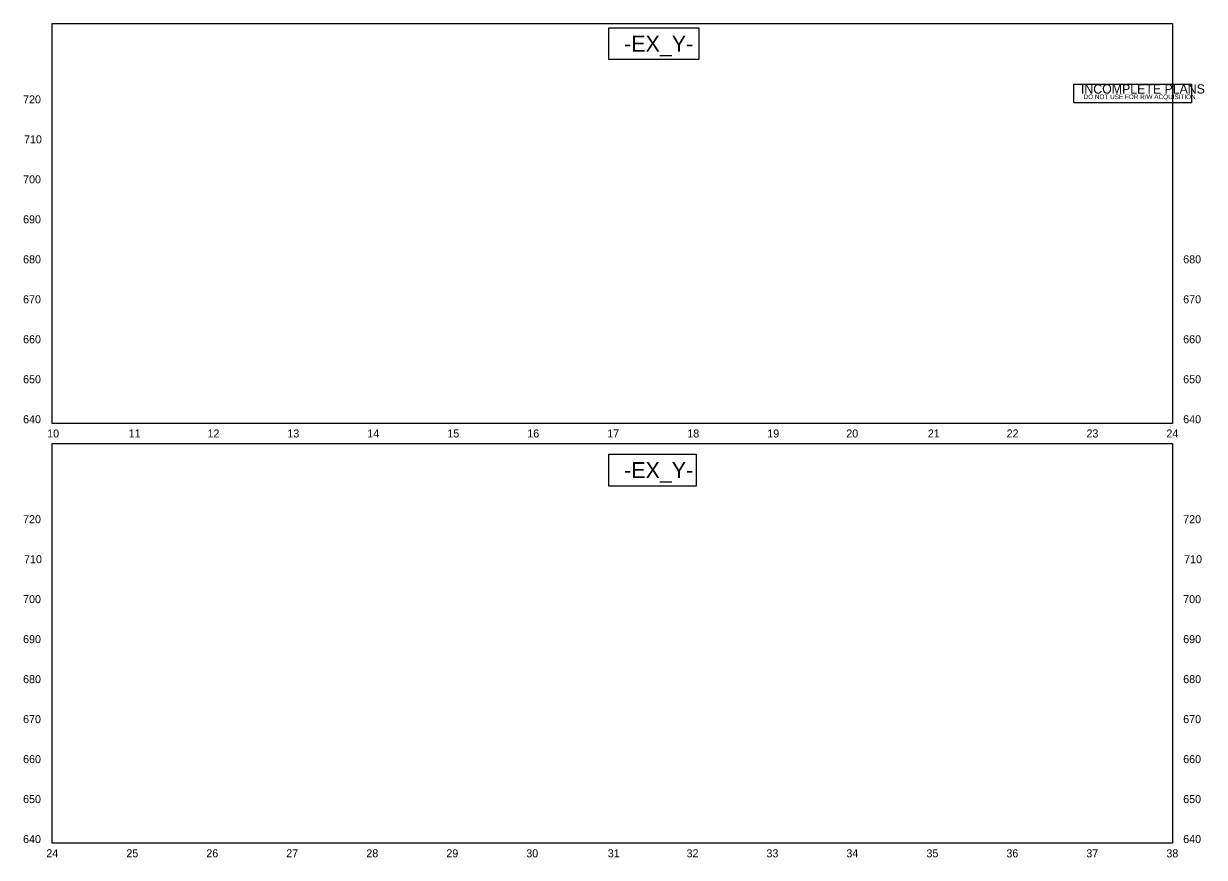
# Model space of a CAD drawing. Extents: x 2472548 to 2478566, y 619381 to 625389.
# Drawn here: x 2477090 to 2478566, y 620488 to 621531 of the extents above; entities that cross this region are included whole.
import ezdxf

# ---------------------------------------------------------------- set-up
doc = ezdxf.new("R2010")
doc.units = 0
for name, color, linetype in [('Default', 7, 'Continuous'), ('ENG SEALS CELL', 7, 'Continuous'), ('Prop Grid Mask', 7, 'Continuous'), ('Prop VPI Label', 7, 'Continuous'), ('Scratch_Level_3', 7, 'Continuous'), ('Sheet PE Seal Cell', 7, 'Continuous')]:
    doc.layers.add(name, color=color, linetype=linetype)

msp = doc.modelspace()

# ---------------------------------------------------------------- linework, layer by layer
at = {"layer": 'Default'}
msp.add_lwpolyline([(2478402.4, 621432), (2478402.4, 621455.5), (2478549.4, 621455.5), (2478549.4, 621432)], close=True, dxfattribs=at)
at = {"layer": 'ENG SEALS CELL'}
for points in [[(2477125.6, 621531.1), (2478525.6, 621531.1), (2478525.6, 621031.1), (2477125.6, 621031.1)], [(2477125.6, 621006.1), (2478525.6, 621006.1), (2478525.6, 620506.1), (2477125.6, 620506.1)]]:
    msp.add_lwpolyline(points, close=True, dxfattribs=at)
at = {"layer": 'Prop Grid Mask'}
for points in [[(2477821.2, 621525.9), (2477933.8, 621525.9), (2477933.8, 621486.1), (2477821.2, 621486.1)], [(2477821.2, 620992.7), (2477930.5, 620992.7), (2477930.5, 620952.8), (2477821.2, 620952.8)]]:
    msp.add_lwpolyline(points, close=True, dxfattribs=at)

# ---------------------------------------------------------------- texts
at = {"layer": 'Default'}
for s, height, p in [('INCOMPLETE PLANS', 11.52, (2478411.3, 621443.7)), ('DO NOT USE FOR R/W ACQUISITION', 5.76, (2478414.6, 621436.7))]:
    msp.add_text(s, height=height, dxfattribs=at).set_placement(p)
at = {"layer": 'Prop VPI Label'}
for p in [(2477840.4, 621496), (2477840.4, 620962.8)]:
    msp.add_text('-EX_Y-', height=20, rotation=0.0003, dxfattribs=at).set_placement(p)
at = {"layer": 'Scratch_Level_3'}
for s, p in [('10', (2477119.2, 621013.6)), ('11', (2477221.1, 621013.6)), ('12', (2477319.6, 621013.6)), ('13', (2477419.4, 621013.6)), ('14', (2477519.3, 621013.6)), ('15', (2477619.4, 621013.6)), ('16', (2477719.3, 621013.6)), ('17', (2477819.2, 621013.6)), ('18', (2477919.3, 621013.6)), ('19', (2478019.3, 621013.6)), ('20', (2478118, 621013.6)), ('21', (2478219.9, 621013.6)), ('22', (2478318.4, 621013.6)), ('23', (2478418.2, 621013.6)), ('24', (2478518.1, 621013.6)), ('24', (2478518.1, 621013.6)), ('24', (2478518.1, 621013.6)), ('24', (2477118.1, 620488.6)), ('25', (2477218.2, 620488.6)), ('26', (2477318.1, 620488.6)), ('27', (2477418, 620488.6)), ('28', (2477518.1, 620488.6)), ('29', (2477618.1, 620488.6)), ('30', (2477718, 620488.6)), ('31', (2477819.9, 620488.6)), ('32', (2477918.4, 620488.6)), ('33', (2478018.2, 620488.6)), ('34', (2478118.1, 620488.6)), ('35', (2478218.2, 620488.6)), ('36', (2478318.1, 620488.6)), ('37', (2478418, 620488.6)), ('38', (2478518.1, 620488.6))]:
    msp.add_text(s, height=10, dxfattribs=at).set_placement(p)
at = {"layer": 'Sheet PE Seal Cell'}
for s, p in [('720', (2477089.1, 621431.4)), ('710', (2477090.3, 621381.4)), ('700', (2477089.1, 621331.4)), ('690', (2477089.1, 621281.4)), ('680', (2477089.1, 621231.4)), ('680', (2478539.1, 621231.4)), ('670', (2477089.1, 621181.4)), ('670', (2478539.1, 621181.4)), ('660', (2477089.1, 621131.4)), ('660', (2478539.1, 621131.4)), ('650', (2477089.1, 621081.4)), ('650', (2478539.1, 621081.4)), ('640', (2477089.1, 621031.4)), ('640', (2478539.1, 621031.4)), ('720', (2477089.1, 620906.4)), ('720', (2478539.1, 620906.4)), ('710', (2477090.3, 620856.4)), ('710', (2478540.3, 620856.4)), ('700', (2477089.1, 620806.4)), ('700', (2478539.1, 620806.4)), ('690', (2477089.1, 620756.4)), ('690', (2478539.1, 620756.4)), ('680', (2477089.1, 620706.4)), ('680', (2478539.1, 620706.4)), ('670', (2477089.1, 620656.4)), ('670', (2478539.1, 620656.4)), ('660', (2477089.1, 620606.4)), ('660', (2478539.1, 620606.4)), ('650', (2477089.1, 620556.4)), ('650', (2478539.1, 620556.4)), ('640', (2477089.1, 620506.4)), ('640', (2478539.1, 620506.4))]:
    msp.add_text(s, height=10, dxfattribs=at).set_placement(p)

doc.saveas('drawing.dxf')
